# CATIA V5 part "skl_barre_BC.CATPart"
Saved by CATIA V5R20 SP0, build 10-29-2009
Part number: skl_barre_BC
Publications: "Droite_BC", "Axe_pivot_BC_B", "Axe_pivot_BC_C"
Bounding box of the stored display mesh (mm): x 0 to 5, y -61 to 31, z 144 to 206
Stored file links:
  D:\Dropbox\IAO_2012\IAO_2012_742_prousseau\skl_barre_BC.CATPart
  D:\Dropbox\IAO_2012\IAO_2012_742_prousseau\skl_barre_AB.CATPart
  D:\Dropbox\IAO_2012\IAO_2012_742_prousseau\skl_IAO.CATProduct
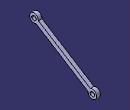
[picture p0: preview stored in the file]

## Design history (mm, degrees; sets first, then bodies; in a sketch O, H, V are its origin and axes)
Set1
  Point1 "Point_B": linked copy from another document
Set2
  Line1 "Droite_BC": type PtPt, FirstPoint Point2, SecondPoint Point3
  Point2 "Point_B": stored without definition
  Point3 "Point_C": stored without definition
  Line2 "Axe_pivot_BC_B": type Normal, RefPoint Point2, RefSkin Plane1, Start -20, End 20
  Plane1 "Plan_Ref": stored without definition
  Line3 "Axe_pivot_BC_C": type Normal, RefPoint Point3, RefSkin Plane1, Start -20, End 20
Body1 (main body)
  Sketch1 on Plane1, origin (0, 0, 0), H (0, 1, 0), V (0, 0, 1)
    line L1 (-52.1837, 194.702) -> (19.0037, 150.21)
    line L2 (22.1837, 155.298) -> (-49.0037, 199.79)
    reference projected line E1 (-55, 200) -> (25, 150) from Line1
    reference projected line E2 (-55, 200) -> (25, 150) from Line1
    reference projected line E3 (-55, 200) -> (25, 150) from Line1
    arc A1 centre (25, 150) radius 6 from (19.0037, 150.21) to (22.1837, 155.298) ccw
    point P1 (25, 150)
    reference projected point E4 (25, 150) from Point3
    circle A2 centre (25, 150) radius 3
    point P2 (25, 150)
    reference projected point E5 (25, 150) from Point3
    circle A3 centre (-55, 200) radius 3
    point P5 (-55, 200)
    reference projected point E6 (-55, 200) from Point1
    arc A4 centre (-55, 200) radius 6 from (-49.0037, 199.79) to (-52.1837, 194.702) ccw
    point P6 (-55, 200)
    reference projected point E7 (-55, 200) from Point1
    distance L2 E3 = 3
    radius A2 = 3
    radius A1 = 6
    radius A3 = 3
    radius A4 = 6
    parallelism: L1 L2, L1 E1
    symmetry: L1 L2 E2
    coincidence: P1 E4, P2 E5, P5 E6, E7 P6
  Pad1: profile Sketch1, direction (1, 0, 0), length 5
